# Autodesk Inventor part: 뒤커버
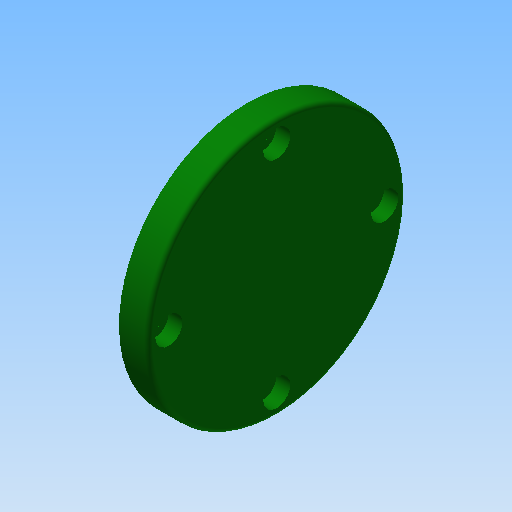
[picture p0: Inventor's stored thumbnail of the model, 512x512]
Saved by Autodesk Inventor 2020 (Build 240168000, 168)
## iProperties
Created: 2015-09
Part Number: 뒤커버
Material: 알루미늄 6061
Document SubType Name: Modeling
Designer: mduedu
Density: 2.71 g/cm^3
Mass: 54.0417 g
Surface Area: 84.9688 cm^2
Volume: 19.9416 cm^3
Appearance: 진녹색
Author: mduedu
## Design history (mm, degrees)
sketch "스케치1"
  geometry: L1 (-15.5, 47)-(-15.5, 78); L2 (-15.5, 78)-(-22.5, 78); L3 (-22.5, 78)-(-22.5, 67); L4 (-25.5, 67)-(-25.5, 47); L5 (-79.5, 39.5)-(-79.5, 54.5) reference; L6 (48.5, 54.5)-(48.5, 39.5) reference; L7 (-79.5, 47)-(48.5, 47); L8 (-22.5, 67)-(-25.5, 67); L9 (-25.5, 47)-(-15.5, 47); 1 further point
  constraints: 14 end point, 4 midpoint, 3 parallel, 1 collinear, 1 point on line, 1 vertical
  dimensions: "d6" = 62 diameter of L2 L7; "d7" = 7 distance of L1.end L2.end; "d8" = 40 diameter of L3.end L7; "d32" = 10 distance between parallel lines of L1 L4
revolve "회전1" sketch "스케치1" stored, may be unused: angle "d4" = 90 deg
sketch "스케치4"
  geometry: C1 r 31 at (0, 0) reference; 2 further points
  constraints: 1 coincident
hole "구멍3" sketch "스케치4" at (0, 0) diameter "d33" = 33; stored, may be unused: countersink angle "d37" = 90 deg, drill point angle "d39" = 0 deg; dims "d34" = 6, "d35" = 4, "d36" = 2, "d38" = 5
fillet "모깎기4" dims "d40" = 1, "d61" = 3
chamfer "모따기2" distance "d41" = 1; stored, may be unused: second distance "d42" = 2, angle "d43" = 45 deg
sketch "스케치6" dims "d56" = 52
  geometry: C1 r 31 at (0, 0) reference; 5 further points
  constraints: 2 vertical alignment, 1 coincident, 7 other
  dimensions: "d59" = 360 deg dimension on C1.centre point (0, 26) (derived)
hole "구멍4" sketch "스케치6" at (0, 26), (-26, 0), (0, -26), (26, 0) diameter "d49" = 3.4; stored, may be unused: countersink angle "d53" = 90 deg, drill point angle "d55" = 0 deg; dims "d50" = 6, "d51" = 6.5, "d52" = 3.4, "d54" = 8
node "솔리드1"
node "참조1"
node "참조2"
